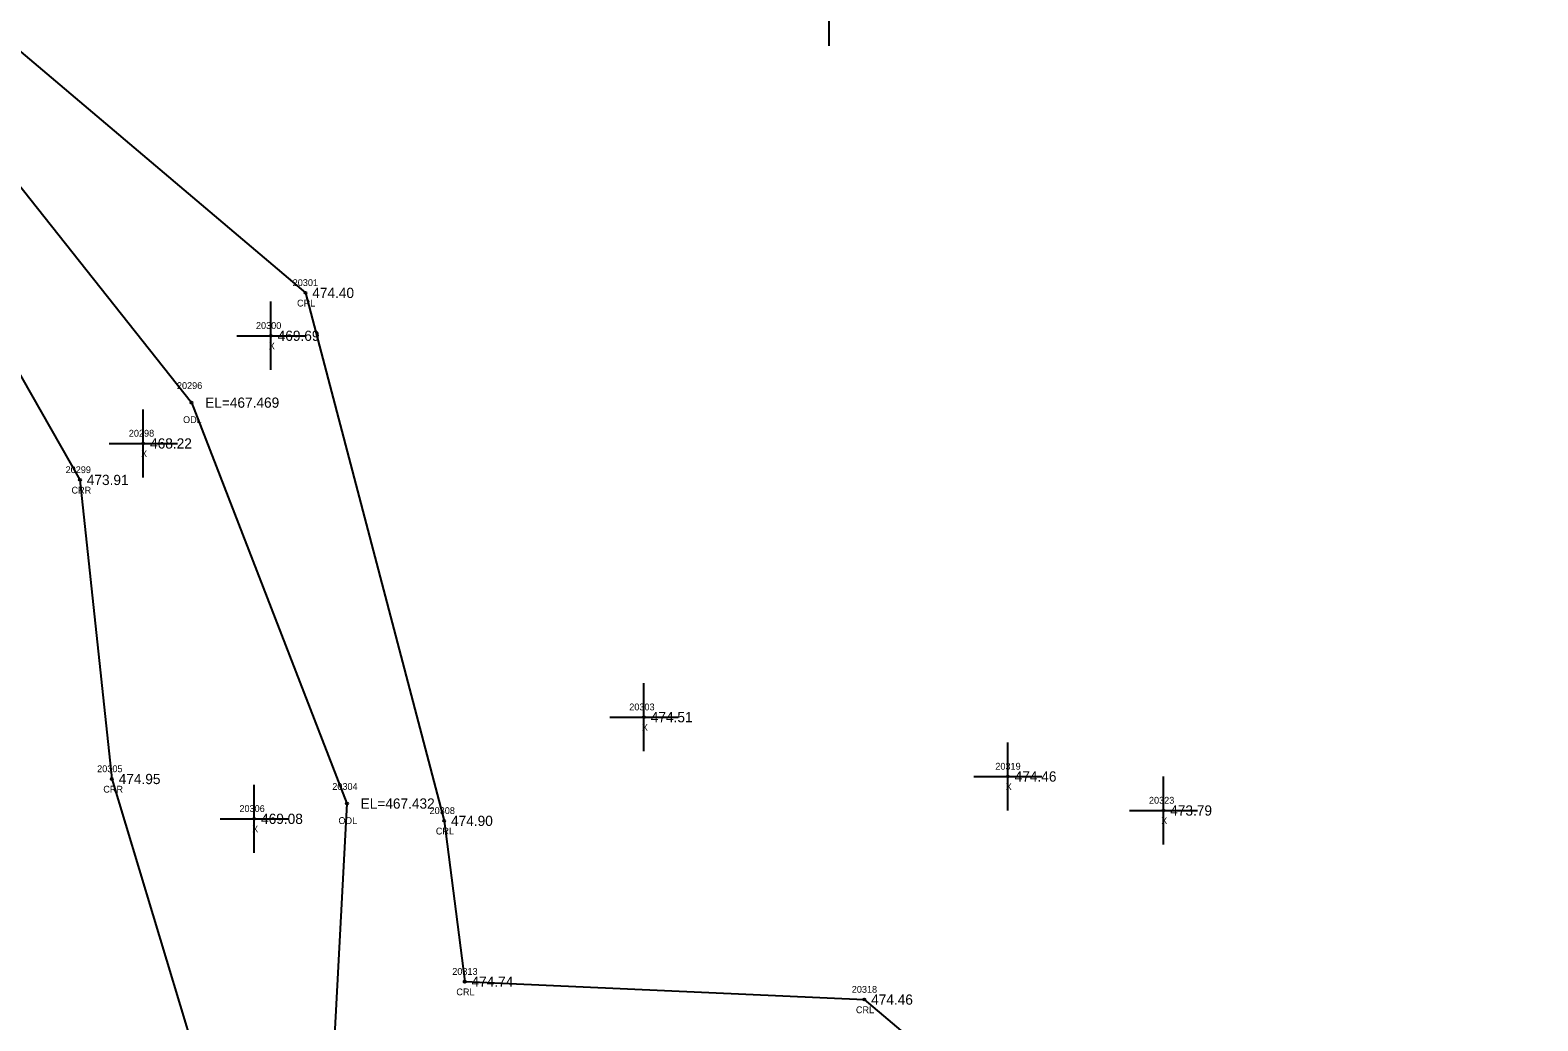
# Model space of a CAD drawing. Extents: x 1789565 to 1790548, y 909019 to 910194.
# Drawn here: x 1790081.8 to 1790303.1, y 909461.5 to 909606.8 of the extents above; entities that cross this region are included whole.
import ezdxf

# ---------------------------------------------------------------- set-up
doc = ezdxf.new("R2010")
doc.units = 0
for name, color, linetype in [('RD_EX_H2O', 7, 'Continuous'), ('RD_EX_H2O_txCode', 7, 'Continuous'), ('RD_EX_Misc', 7, 'Continuous'), ('RD_EX_Misc_txCode', 7, 'Continuous'), ('RD_EX_TX_H2O_ELEV', 7, 'Continuous'), ('RD_EX_TX_Misc_ELEV', 7, 'Continuous'), ('RD_SMD_Locator', 7, 'Continuous')]:
    doc.layers.add(name, color=color, linetype=linetype)

msp = doc.modelspace()

# ---------------------------------------------------------------- linework, layer by layer
at = {"layer": 'RD_EX_H2O'}
for points in [[(1789926.75, 910151.78), (1789921.87, 910061.22), (1789923.33, 910015.8), (1789922.65, 909953.15), (1789957.79, 909859.65), (1789976.3, 909811.78), (1790009.05, 909737.59), (1790033.3, 909656.58), (1790043.84, 909640.77), (1790040.94, 909620.44), (1790068.41, 909598.88), (1790105.46, 909552.21), (1790128.28, 909493.4), (1790125.72, 909445.59), (1790167.31, 909436.17), (1790202.14, 909447.88), (1790216.41, 909437.36), (1790196.97, 909382.86), (1790209.47, 909371.8), (1790248.65, 909379.51), (1790333.47, 909404.65), (1790412.72, 909370.84), (1790438.82, 909377.48), (1790480.23, 909327.32)], [(1789942.19, 910149.47), (1789928.94, 910061.47), (1789937.03, 910016.56), (1789929.09, 909954.8), (1789962.46, 909861.74), (1789984.97, 909814.65), (1790017.82, 909740.15), (1790045.4, 909660.05), (1790055.69, 909646.96), (1790055.38, 909644.82), (1790053.69, 909634.91), (1790054.91, 909627.64), (1790075.55, 909607.72), (1790122.18, 909568.31), (1790142.55, 909490.86), (1790145.56, 909467.27), (1790204.21, 909464.64), (1790228.21, 909444.34), (1790208.83, 909385.44), (1790245.53, 909398.45), (1790340.56, 909420.98), (1790422.56, 909390.06), (1790444.95, 909390.88), (1790496, 909329.5)], [(1790030.97, 909616.21), (1790039.23, 909609.17), (1790060.86, 909590.41), (1790089.09, 909540.87), (1790093.77, 909497), (1790113.81, 909430.51), (1790177.09, 909424.59), (1790197.54, 909430.06), (1790185.17, 909386.39), (1790196.62, 909365.47), (1790247.61, 909363.63), (1790324.38, 909372.65), (1790407.18, 909352.01), (1790424.72, 909347.04), (1790471.09, 909309.36)]]:
    msp.add_lwpolyline(points, dxfattribs=at)
at = {"layer": 'RD_EX_Misc'}
for p, q in [((1790199.04, 909604.55), (1790199.04, 909614.55)), ((1790117.11, 909557.02), (1790117.11, 909567.02)), ((1790112.11, 909562.02), (1790122.11, 909562.02)), ((1790098.38, 909541.22), (1790098.38, 909551.22)), ((1790093.38, 909546.22), (1790103.38, 909546.22)), ((1790171.87, 909501.07), (1790171.87, 909511.07)), ((1790166.87, 909506.07), (1790176.87, 909506.07)), ((1790225.28, 909492.37), (1790225.28, 909502.37)), ((1790220.28, 909497.37), (1790230.28, 909497.37)), ((1790248.11, 909487.38), (1790248.11, 909497.38)), ((1790114.67, 909486.16), (1790114.67, 909496.16)), ((1790109.67, 909491.16), (1790119.67, 909491.16)), ((1790243.11, 909492.38), (1790253.11, 909492.38))]:
    msp.add_line(p, q, dxfattribs=at)
at = {"layer": 'RD_SMD_Locator'}
for centre in [(1790122.18, 909568.31), (1790117.11, 909562.02), (1790105.46, 909552.21), (1790098.38, 909546.22), (1790089.09, 909540.87), (1790171.87, 909506.07), (1790093.77, 909497), (1790225.28, 909497.37), (1790128.28, 909493.4), (1790114.67, 909491.16), (1790142.55, 909490.86), (1790248.11, 909492.38), (1790145.56, 909467.27), (1790204.21, 909464.64)]:
    msp.add_circle(centre, 0.15, dxfattribs=at)

# ---------------------------------------------------------------- texts
at = {"layer": 'RD_EX_H2O_txCode'}
for s, p in [('20301', (1790120.31, 909569.31)), ('CRL', (1790120.95, 909566.31)), ('20296', (1790103.32, 909554.21)), ('ODL', (1790104.22, 909549.21)), ('20299', (1790086.98, 909541.87)), ('CRR', (1790087.84, 909538.87)), ('20305', (1790091.61, 909498)), ('CRR', (1790092.51, 909495)), ('20304', (1790126.12, 909495.4)), ('20308', (1790140.4, 909491.86)), ('ODL', (1790127.03, 909490.4)), ('CRL', (1790141.32, 909488.86)), ('20313', (1790143.73, 909468.27)), ('CRL', (1790144.33, 909465.27)), ('20318', (1790202.37, 909465.64)), ('CRL', (1790202.98, 909462.64))]:
    msp.add_text(s, height=1, dxfattribs=at).set_placement(p)
at = {"layer": 'RD_EX_Misc_txCode'}
for s, p in [('20300', (1790114.92, 909563.02)), ('X', (1790116.8, 909560.02)), ('20298', (1790096.26, 909547.22)), ('X', (1790098.06, 909544.22)), ('20303', (1790169.71, 909507.07)), ('X', (1790171.56, 909504.07)), ('20319', (1790223.44, 909498.37)), ('X', (1790224.96, 909495.37)), ('20306', (1790112.49, 909492.16)), ('20323', (1790245.99, 909493.38)), ('X', (1790247.79, 909490.38)), ('X', (1790114.36, 909489.16))]:
    msp.add_text(s, height=1, dxfattribs=at).set_placement(p)
at = {"layer": 'RD_EX_TX_H2O_ELEV'}
for s, p in [('474.40', (1790123.18, 909567.56)), ('EL=467.469', (1790107.46, 909551.46)), ('473.91', (1790090.09, 909540.12)), ('474.95', (1790094.77, 909496.25)), ('EL=467.432', (1790130.28, 909492.65)), ('474.90', (1790143.55, 909490.11)), ('474.74', (1790146.56, 909466.52)), ('474.46', (1790205.21, 909463.89))]:
    msp.add_text(s, height=1.5, dxfattribs=at).set_placement(p)
at = {"layer": 'RD_EX_TX_Misc_ELEV'}
for s, p in [('469.69', (1790118.11, 909561.27)), ('468.22', (1790099.38, 909545.47)), ('474.51', (1790172.87, 909505.32)), ('474.46', (1790226.28, 909496.62)), ('473.79', (1790249.11, 909491.63)), ('469.08', (1790115.67, 909490.41))]:
    msp.add_text(s, height=1.5, dxfattribs=at).set_placement(p)

doc.saveas('drawing.dxf')
